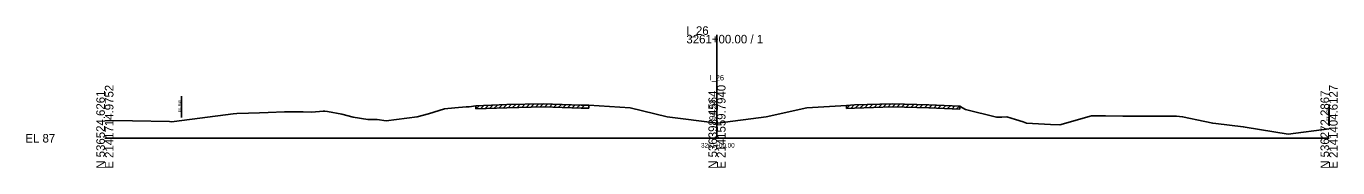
# Model space of a CAD drawing. Extents: x -13101 to 4803, y -924 to 22390.
# Drawn here: x 2974.3 to 3402.8, y 10490.3 to 10536.7 of the extents above; entities that cross this region are included whole.
import ezdxf

# ---------------------------------------------------------------- set-up
doc = ezdxf.new("R2010")
doc.units = 0
for name, color, linetype in [('RD_GPK_XS_Cell', 7, 'Continuous'), ('RD_XS_ExGround', 7, 'Continuous'), ('RD_XS_ExPaveRet', 7, 'Continuous'), ('RD_XS_ExRW', 7, 'Continuous'), ('RD_XS_TX_Baseline', 7, 'Continuous'), ('RD_XS_TX_Elev_EX', 7, 'Continuous'), ('RD_XS_TX_Station', 7, 'Continuous')]:
    doc.layers.add(name, color=color, linetype=linetype)

msp = doc.modelspace()

# ---------------------------------------------------------------- linework, layer by layer
at = {"layer": 'RD_GPK_XS_Cell'}
for p, q in [((3200, 10500), (3200, 10533.85)), ((3000, 10500), (3200, 10500)), ((3200, 10500), (3400, 10500))]:
    msp.add_line(p, q, dxfattribs=at)
at = {"layer": 'RD_XS_ExGround'}
msp.add_lwpolyline([(3000, 10505.74), (3001.37, 10505.79), (3001.85, 10505.82), (3009.04, 10505.68), (3021.15, 10505.43), (3021.86, 10505.41), (3022.68, 10505.52), (3041.87, 10508), (3043.09, 10508.06), (3046.91, 10508.21), (3050.54, 10508.32), (3053.33, 10508.43), (3058.67, 10508.69), (3060.94, 10508.67), (3061.88, 10508.69), (3064.81, 10508.6), (3067.61, 10508.5), (3071.38, 10508.88), (3071.88, 10508.9), (3072.72, 10508.76), (3077.47, 10507.88), (3081.12, 10506.94), (3085.96, 10506.18), (3089.02, 10506.13), (3091.87, 10505.74), (3102.06, 10506.96), (3105.7, 10508.04), (3110.93, 10509.62), (3114.3, 10509.92), (3118.03, 10510.23), (3119.07, 10510.33), (3121.23, 10510.6), (3131.37, 10510.99), (3143.26, 10511.28), (3155.63, 10510.87), (3158.1, 10510.82), (3171.62, 10509.95), (3183.77, 10507.01), (3200.15, 10504.91), (3216.08, 10507.01), (3229.33, 10509.92), (3242.31, 10510.76), (3244.94, 10510.89), (3257.39, 10511.23), (3269.23, 10510.95), (3279.37, 10510.54), (3280.25, 10509.9), (3281.16, 10509.43), (3291.35, 10506.86), (3293.1, 10506.93), (3294.74, 10506.99), (3297.52, 10506.15), (3300, 10505.32), (3301.11, 10504.94), (3308.94, 10504.53), (3312.01, 10504.36), (3322.37, 10507.37), (3327, 10507.31), (3332.57, 10507.24), (3335.39, 10507.26), (3339.27, 10507.19), (3341.38, 10507.22), (3341.99, 10507.23), (3349.06, 10507.17), (3350.15, 10507.18), (3352.12, 10507.01), (3359.36, 10505.51), (3362, 10504.89), (3363.04, 10504.78), (3371.98, 10503.75), (3372.55, 10503.63), (3386.59, 10501.32), (3400, 10503.08)], dxfattribs=at)
at = {"layer": 'RD_XS_ExPaveRet'}
for p, q in [((3121.23, 10509.6), (3122.27, 10510.64)), ((3121.23, 10509.6), (3121.23, 10510.6)), ((3121.23, 10509.6), (3131.37, 10509.99)), ((3122.73, 10509.65), (3123.77, 10510.69)), ((3124.23, 10509.71), (3125.27, 10510.75)), ((3125.73, 10509.77), (3126.77, 10510.81)), ((3127.23, 10509.83), (3128.27, 10510.87)), ((3128.73, 10509.89), (3129.77, 10510.92)), ((3130.23, 10509.94), (3131.27, 10510.98)), ((3131.37, 10509.99), (3143.26, 10510.28)), ((3131.73, 10510), (3132.75, 10511.02)), ((3133.23, 10510.03), (3134.25, 10511.06)), ((3134.73, 10510.07), (3135.75, 10511.1)), ((3136.23, 10510.11), (3137.25, 10511.13)), ((3137.73, 10510.15), (3138.75, 10511.17)), ((3139.23, 10510.18), (3140.25, 10511.21)), ((3140.73, 10510.22), (3141.75, 10511.25)), ((3142.23, 10510.26), (3143.25, 10511.28)), ((3143.26, 10510.28), (3155.63, 10509.87)), ((3143.73, 10510.27), (3144.69, 10511.24)), ((3145.23, 10510.22), (3146.19, 10511.19)), ((3146.73, 10510.17), (3147.69, 10511.14)), ((3148.23, 10510.12), (3149.19, 10511.08)), ((3149.73, 10510.07), (3150.69, 10511.03)), ((3151.23, 10510.02), (3152.19, 10510.98)), ((3152.73, 10509.97), (3153.69, 10510.93)), ((3154.23, 10509.92), (3155.19, 10510.88)), ((3155.63, 10509.87), (3158.1, 10509.82)), ((3155.73, 10509.87), (3156.71, 10510.85)), ((3158.1, 10510.82), (3158.1, 10509.82)), ((3242.31, 10509.76), (3243.36, 10510.81)), ((3242.31, 10509.76), (3242.31, 10510.76)), ((3242.31, 10509.76), (3244.94, 10509.89)), ((3243.81, 10509.84), (3244.86, 10510.89)), ((3244.94, 10509.89), (3257.39, 10510.23)), ((3245.31, 10509.9), (3246.33, 10510.93)), ((3246.81, 10509.95), (3247.83, 10510.97)), ((3248.31, 10509.99), (3249.33, 10511.01)), ((3249.81, 10510.03), (3250.83, 10511.06)), ((3251.31, 10510.07), (3252.33, 10511.1)), ((3252.81, 10510.11), (3253.83, 10511.14)), ((3254.31, 10510.15), (3255.33, 10511.18)), ((3255.81, 10510.19), (3256.83, 10511.22)), ((3257.31, 10510.23), (3258.29, 10511.21)), ((3257.39, 10510.23), (3269.23, 10509.95)), ((3258.81, 10510.2), (3259.78, 10511.18)), ((3260.31, 10510.16), (3261.28, 10511.14)), ((3261.81, 10510.13), (3262.78, 10511.11)), ((3263.31, 10510.09), (3264.28, 10511.07)), ((3264.81, 10510.06), (3265.78, 10511.04)), ((3266.31, 10510.02), (3267.28, 10511)), ((3267.81, 10509.99), (3268.78, 10510.97)), ((3269.23, 10509.95), (3279.37, 10509.54)), ((3269.31, 10509.95), (3270.27, 10510.91)), ((3270.81, 10509.89), (3271.77, 10510.85)), ((3272.31, 10509.83), (3273.27, 10510.79)), ((3273.81, 10509.77), (3274.77, 10510.73)), ((3275.31, 10509.7), (3276.27, 10510.66)), ((3276.81, 10509.64), (3277.77, 10510.6)), ((3278.31, 10509.58), (3279.27, 10510.54)), ((3279.37, 10510.54), (3279.37, 10509.54))]:
    msp.add_line(p, q, dxfattribs=at)
at = {"layer": 'RD_XS_ExRW'}
for p, q in [((3025, 10506.82), (3025, 10513.82)), ((3400, 10504.08), (3400, 10511.08))]:
    msp.add_line(p, q, dxfattribs=at)

# ---------------------------------------------------------------- texts
at = {"layer": 'RD_GPK_XS_Cell'}
for s, p in [('3261+00.00 / 1', (3190, 10531.05)), ('I_26', (3190, 10533.85)), ('EL 87', (2974, 10498.6))]:
    msp.add_text(s, height=2.8, dxfattribs=at).set_placement(p)
for s, p in [('E 2141714.9752', (3002.8, 10490)), ('E 2141559.7940', (3202.8, 10490)), ('E 2141404.6127', (3402.8, 10490)), ('N 536524.6261', (3000, 10490)), ('N 536398.4564', (3200, 10490)), ('N 536272.2867', (3400, 10490))]:
    msp.add_text(s, height=2.8, rotation=90, dxfattribs=at).set_placement(p)
at = {"layer": 'RD_XS_ExRW'}
for p in [(3024.75, 10508.5), (3399.75, 10505.76)]:
    msp.add_text('EX. R/W ', height=0.75, rotation=90, dxfattribs=at).set_placement(p)
at = {"layer": 'RD_XS_TX_Baseline'}
msp.add_text('I_26', height=1.75, dxfattribs=at).set_placement((3197.6, 10518.93))
at = {"layer": 'RD_XS_TX_Elev_EX'}
msp.add_text('91.93', height=2, rotation=90, dxfattribs=at).set_placement((3199.5, 10505.93))
at = {"layer": 'RD_XS_TX_Station'}
msp.add_text('3261+00.00', height=1.5, dxfattribs=at).set_placement((3194.79, 10496.93))

doc.saveas('drawing.dxf')
